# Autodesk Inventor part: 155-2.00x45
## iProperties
Created: 2007-06
Part Number: 155-2.00x45
Document SubType Name: Modeling
Designer: btaylor
Density: 1 g/cm^3
Author: btaylor
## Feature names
1. Sweep1
2. Extrusion1
3. Extrusion2
4. Fillet1
5. Fillet2
6. Extrusion3
7. Extrusion4
8. Sweep2
9. Fillet3
10. Fillet4
11. Chamfer1
12. Chamfer2
13. Fillet5
14. Fillet6
